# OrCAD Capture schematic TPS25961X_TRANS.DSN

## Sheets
1 X_DUT: size A
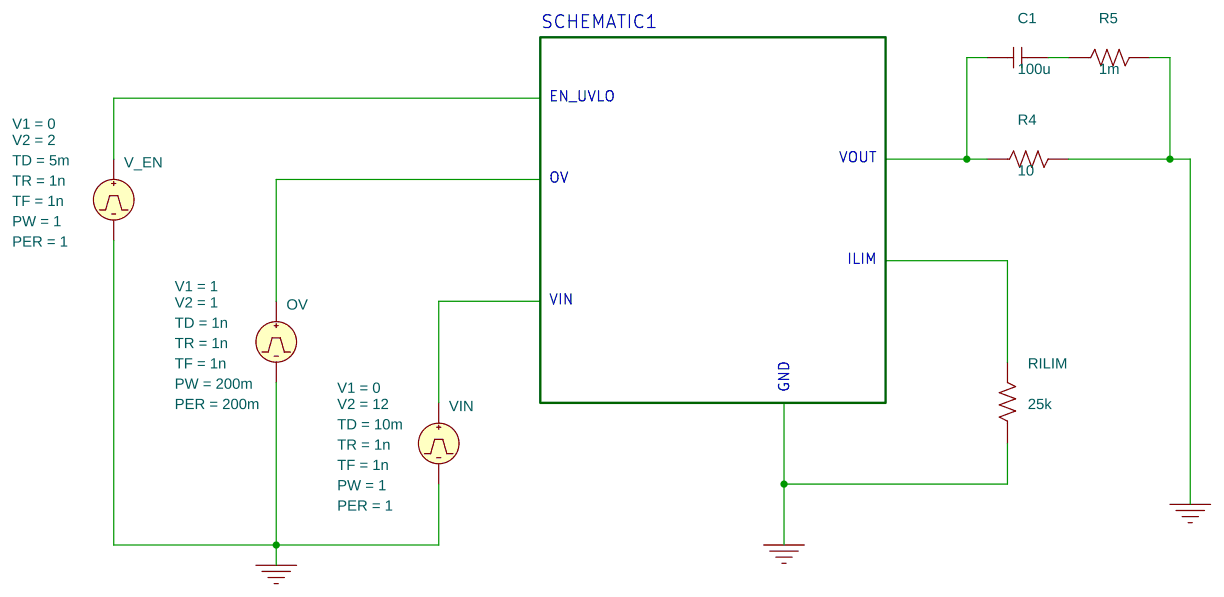
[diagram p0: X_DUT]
2 PAGE1: size C; block SCHEMATIC1
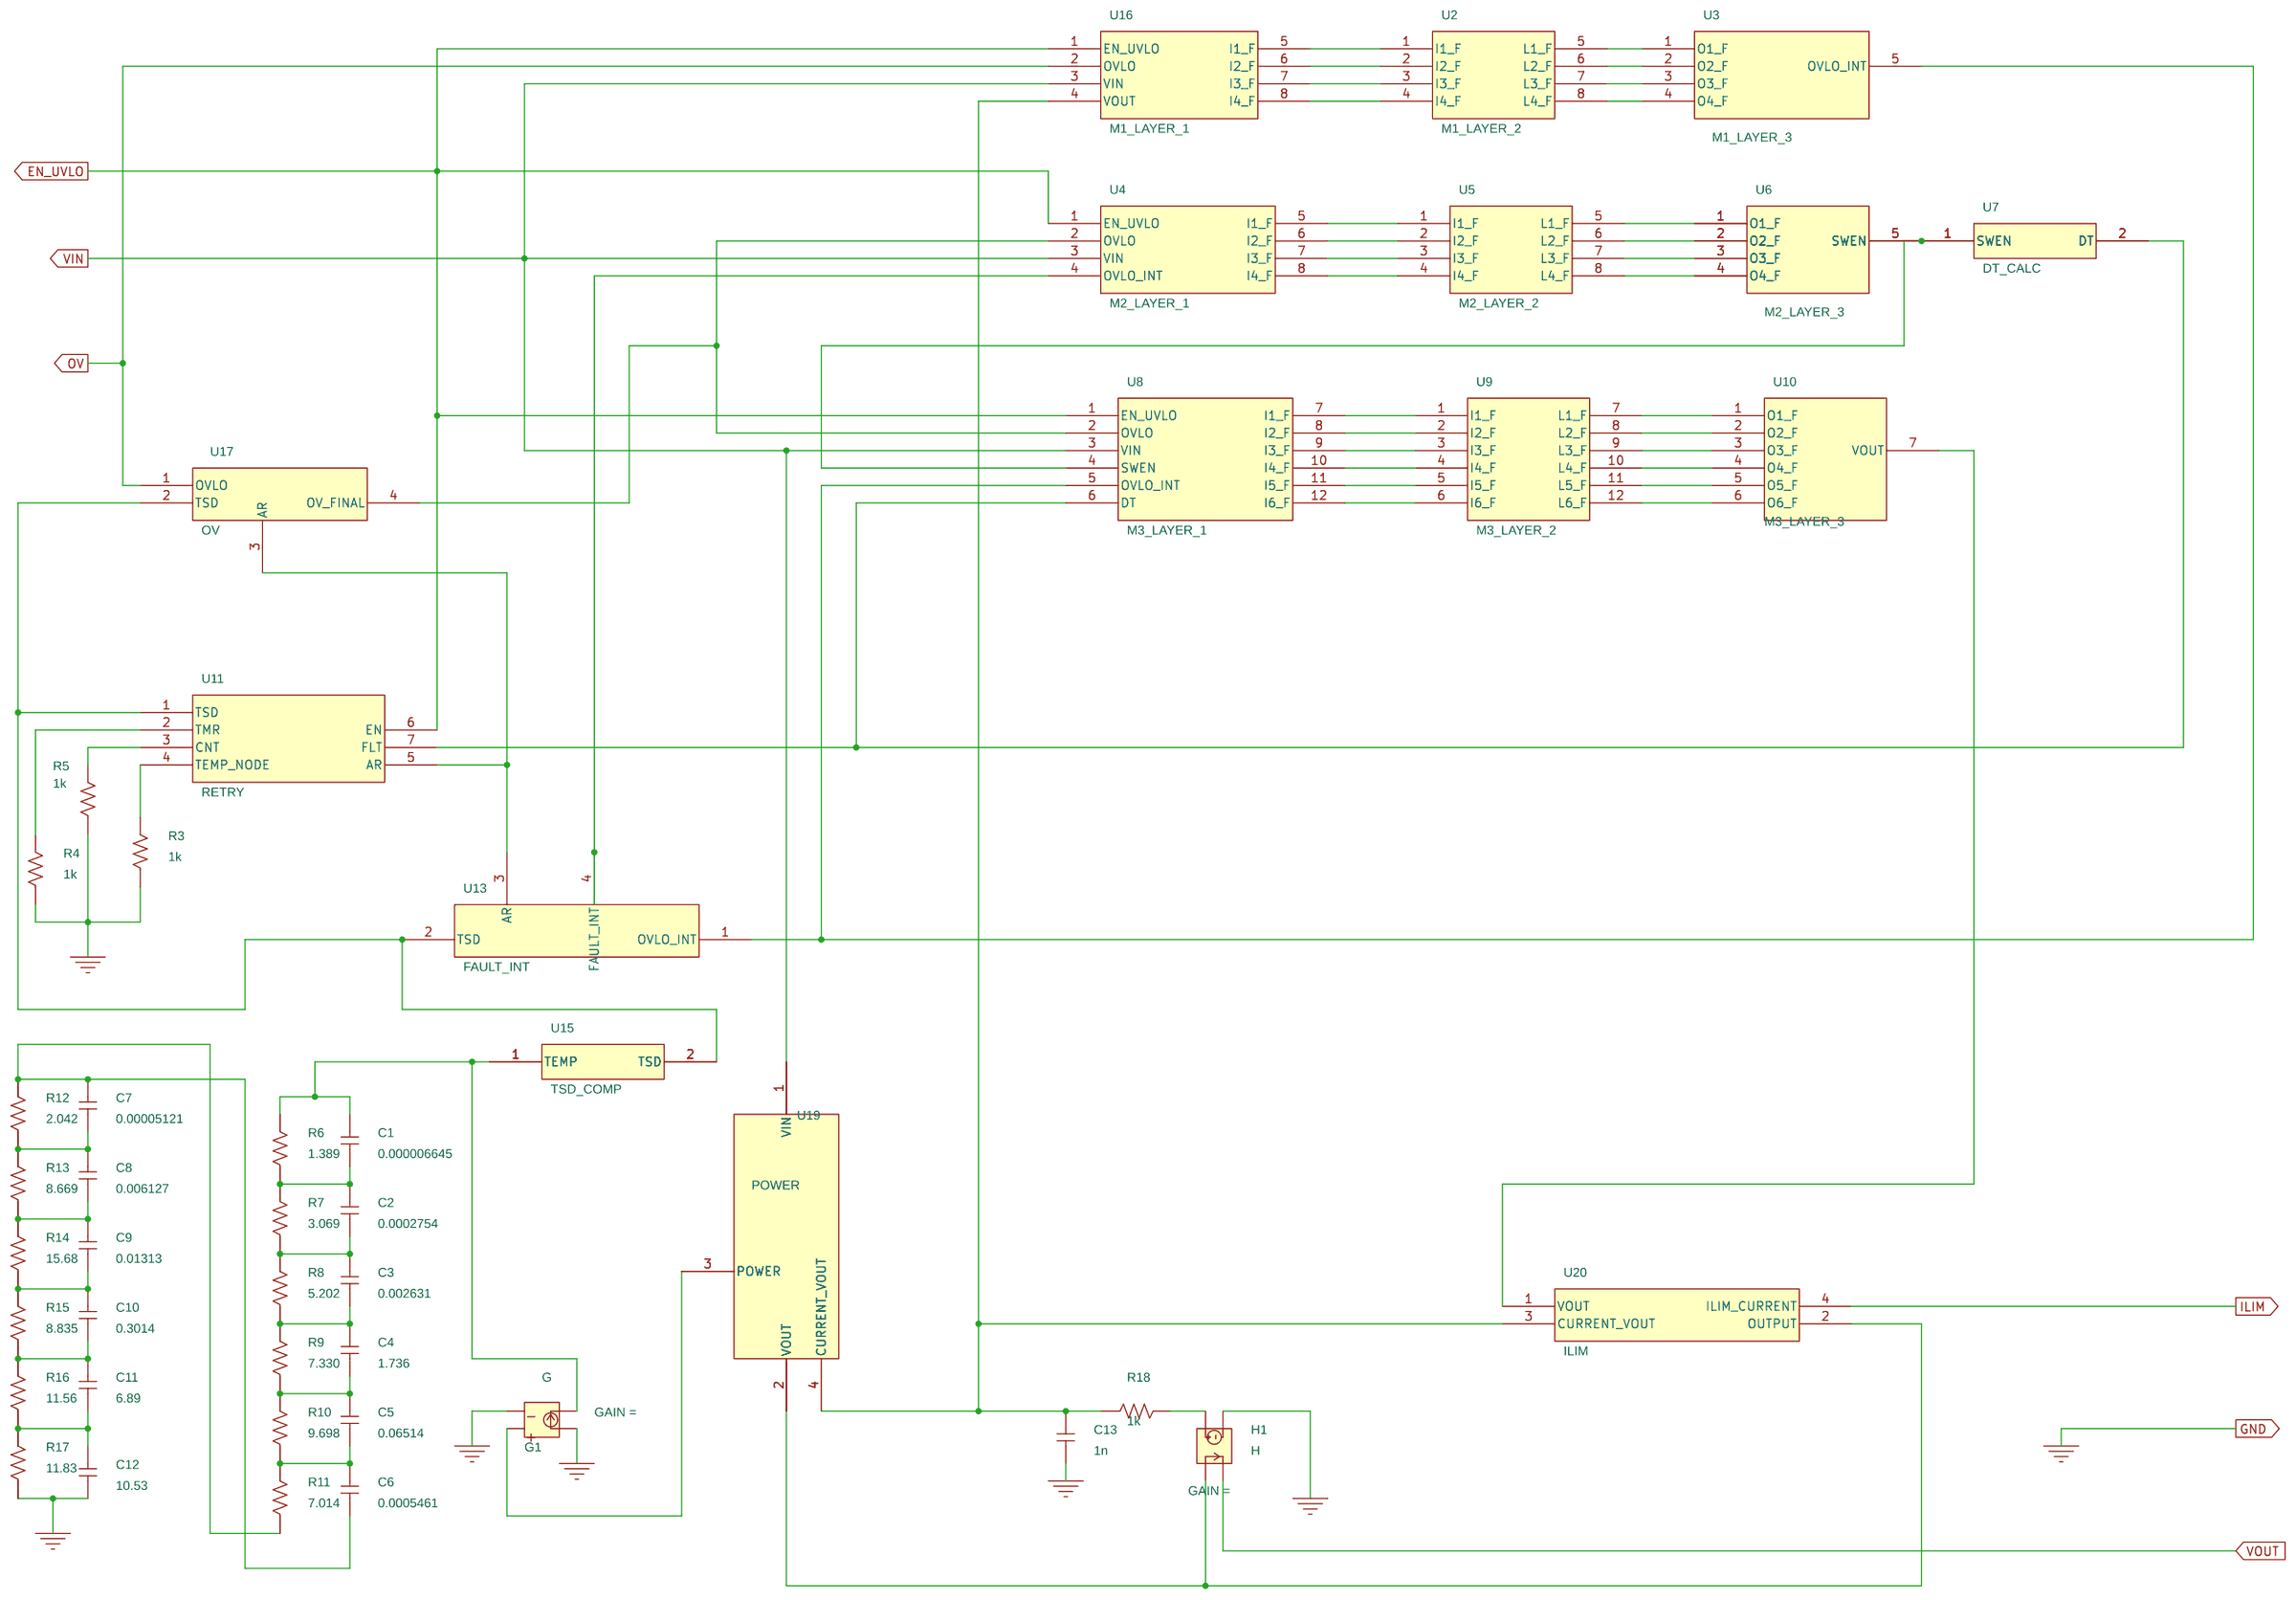
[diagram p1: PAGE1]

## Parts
sheet PAGE1
C1#2  0.000006645  [cap196]
C2  0.0002754  [cap196]
C3  0.002631  [cap196]
C4  1.736  [cap196]
C5  0.06514  [cap196]
C6  0.0005461  [cap196]
C7  0.00005121  [cap196]
C8  0.006127  [cap196]
C9  0.01313  [cap196]
C10  0.3014  [cap196]
C11  6.89  [cap196]
C12  10.53  [cap196]
C13  1n  [cap196]
G1  G
H1  H
R3  1k  [AXRC05]
R4#2  1k  [AXRC05]
R5#2  1k  [AXRC05]
R6  1.389  [AXRC05]
R7  3.069  [AXRC05]
R8  5.202  [AXRC05]
R9  7.330  [AXRC05]
R10  9.698  [AXRC05]
R11  7.014  [AXRC05]
R12  2.042  [AXRC05]
R13  8.669  [AXRC05]
R14  15.68  [AXRC05]
R15  8.835  [AXRC05]
R16  11.56  [AXRC05]
R17  11.83  [AXRC05]
R18  1k  [AXRC05]
U2  M1_LAYER_2
U3  M1_LAYER_3
U4  M2_LAYER_1
U5  M2_LAYER_2
U6  M2_LAYER_3
U7  DT_CALC
U8  M3_LAYER_1
U9  M3_LAYER_2
U10  M3_LAYER_3
U11  RETRY
U13  FAULT_INT
U15  TSD_COMP
U16  M1_LAYER_1
U17  OV
U19  POWER
U20  ILIM
sheet X_DUT
C1  100u  [cap196]
OV  VPULSE
R4  10  [AXRC05]
R5  1m  [AXRC05]
RILIM  25k  [AXRC05]
V_EN  VPULSE
VIN  VPULSE

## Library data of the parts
C1 C1#2 C2-C13 = C
G1 = G
H1 = H
R3 R4 R4#2 R5 R5#2 R6-R18 RILIM = R
U2 = M1_LAYER_2
U3 = M1_LAYER_1
U4 = M2_LAYER_1
U5 = M2_LAYER_2
U6 = M2_LAYER_0
U7 = DT_CALC
U8 = M3_LAYER_1
U9 = M3_LAYER_2
U10 = M3_LAYER_0
U11 = RETRY_0
U13 = FAULT_INT_2
U15 = TSD_COMP
U16 = M1_LAYER_1_v2
U17 = OV_0
U19 = POWER_5
U20 = ILIM_2
OV = VPULSE: PER: 200m; PW: 200m; TD: 1n; TF: 1n; TR: 1n; V1: 1; V2: 1
V_EN = VPULSE: PER: 1; PW: 1; TD: 5m; TF: 1n; TR: 1n; V1: 0; V2: 2
VIN = VPULSE: PER: 1; PW: 1; TD: 10m; TF: 1n; TR: 1n; V1: 0; V2: 12

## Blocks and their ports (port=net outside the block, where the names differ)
SCHEMATIC1 = schematic SCHEMATIC1, on sheet X_DUT: OV=N49287, VOUT=N49193, GND=0, VIN=N49347, ILIM=N49337, EN_UVLO=N49209

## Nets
0: C12.1 C13.1 G1.2 G1.3 H1.4 OV.2(-) R3.1 R4.2 R4#2.1 R5.2 R5#2.1 R17.1 RILIM.1 V_EN.2(-) VIN.2(-)
N49193: C1.1 H1.2 R4.1
N49197: C1.2 R5.1
N49209: U4.1(EN_UVLO) U8.1(EN_UVLO) U11.6(EN) U16.1(EN_UVLO) V_EN.1(+)
N49287: OV.1(+) U16.2(OVLO) U17.1(OVLO)
N49337: RILIM.2 U20.4(ILIM_CURRENT)
N49347: U4.3(VIN) U8.3(VIN) U16.3(VIN) U19.1(VIN) VIN.1(+)
SCHEMATIC1/N93816: U2.1(I1_F) U16.5(I1_F)
SCHEMATIC1/N93820: U2.5(L1_F) U3.1(O1_F)
SCHEMATIC1/N93834: U2.2(I2_F) U16.6(I2_F)
SCHEMATIC1/N93838: U2.6(L2_F) U3.2(O2_F)
SCHEMATIC1/N93842: U3.5(OVLO_INT) U8.5(OVLO_INT) U13.1(OVLO_INT)
SCHEMATIC1/N93858: U2.3(I3_F) U16.7(I3_F)
SCHEMATIC1/N93862: U2.7(L3_F) U3.3(O3_F)
SCHEMATIC1/N93866: C13.2 R18.1 U16.4(VOUT) U19.4(CURRENT_VOUT) U20.3(CURRENT_VOUT)
SCHEMATIC1/N93874: U2.4(I4_F) U16.8(I4_F)
SCHEMATIC1/N93878: U2.8(L4_F) U3.4(O4_F)
SCHEMATIC1/N94030: U4.5(I1_F) U5.1(I1_F)
SCHEMATIC1/N94034: U5.5(L1_F) U6.1(O1_F)
SCHEMATIC1/N94066: U4.2(OVLO) U8.2(OVLO) U17.4(OV_FINAL)
SCHEMATIC1/N94076: U4.6(I2_F) U5.2(I2_F)
SCHEMATIC1/N94080: U5.6(L2_F) U6.2(O2_F)
SCHEMATIC1/N94084: U6.5(SWEN) U7.1(SWEN) U8.4(SWEN)
SCHEMATIC1/N94092: U7.2(DT) U8.6(DT) U11.7(FLT)
SCHEMATIC1/N94116: U4.7(I3_F) U5.3(I3_F)
SCHEMATIC1/N94120: U5.7(L3_F) U6.3(O3_F)
SCHEMATIC1/N94124: U4.4(OVLO_INT) U13.4(FAULT_INT)
SCHEMATIC1/N94132: U4.8(I4_F) U5.4(I4_F)
SCHEMATIC1/N94136: U5.8(L4_F) U6.4(O4_F)
SCHEMATIC1/N94348: U8.7(I1_F) U9.1(I1_F)
SCHEMATIC1/N94352: U9.7(L1_F) U10.1(O1_F)
SCHEMATIC1/N94360: U8.8(I2_F) U9.2(I2_F)
SCHEMATIC1/N94364: U9.8(L2_F) U10.2(O2_F)
SCHEMATIC1/N94380: U8.9(I3_F) U9.3(I3_F)
SCHEMATIC1/N94384: U9.9(L3_F) U10.3(O3_F)
SCHEMATIC1/N94388: U10.7(VOUT) U20.1(VOUT)
SCHEMATIC1/N94426: U8.10(I4_F) U9.4(I4_F)
SCHEMATIC1/N94430: U9.10(L4_F) U10.4(O4_F)
SCHEMATIC1/N94446: U8.11(I5_F) U9.5(I5_F)
SCHEMATIC1/N94450: U9.11(L5_F) U10.5(O5_F)
SCHEMATIC1/N94454: U11.1(TSD) U13.2(TSD) U15.2(TSD) U17.2(TSD)
SCHEMATIC1/N94474: U8.12(I6_F) U9.6(I6_F)
SCHEMATIC1/N94478: U9.12(L6_F) U10.6(O6_F)
SCHEMATIC1/N94482: U11.5(AR) U13.3(AR) U17.3(AR)
SCHEMATIC1/N94540: R4#2.2 U11.2(TMR)
SCHEMATIC1/N94552: R5#2.2 U11.3(CNT)
SCHEMATIC1/N94572: R3.2 U11.4(TEMP_NODE)
SCHEMATIC1/N94752: C6.1 C7.2 R11.1 R12.2
SCHEMATIC1/N94788: C1#2.2 G1.4 R6.2 U15.1(TEMP)
SCHEMATIC1/N94902: C7.1 C8.2 R12.1 R13.2
SCHEMATIC1/N94988: C1#2.1 C2.2 R6.1 R7.2
SCHEMATIC1/N95006: C8.1 C9.2 R13.1 R14.2
SCHEMATIC1/N95092: C2.1 C3.2 R7.1 R8.2
SCHEMATIC1/N95102: C9.1 C10.2 R14.1 R15.2
SCHEMATIC1/N95144: G1.1 U19.3(POWER)
SCHEMATIC1/N95220: C3.1 C4.2 R8.1 R9.2
SCHEMATIC1/N95244: H1.1 U19.2(VOUT) U20.2(OUTPUT)
SCHEMATIC1/N95252: C10.1 C11.2 R15.1 R16.2
SCHEMATIC1/N95346: C4.1 C5.2 R9.1 R10.2
SCHEMATIC1/N95402: C11.1 C12.2 R16.1 R17.2
SCHEMATIC1/N95468: H1.3 R18.2
SCHEMATIC1/N95582: C5.1 C6.2 R10.1 R11.2
